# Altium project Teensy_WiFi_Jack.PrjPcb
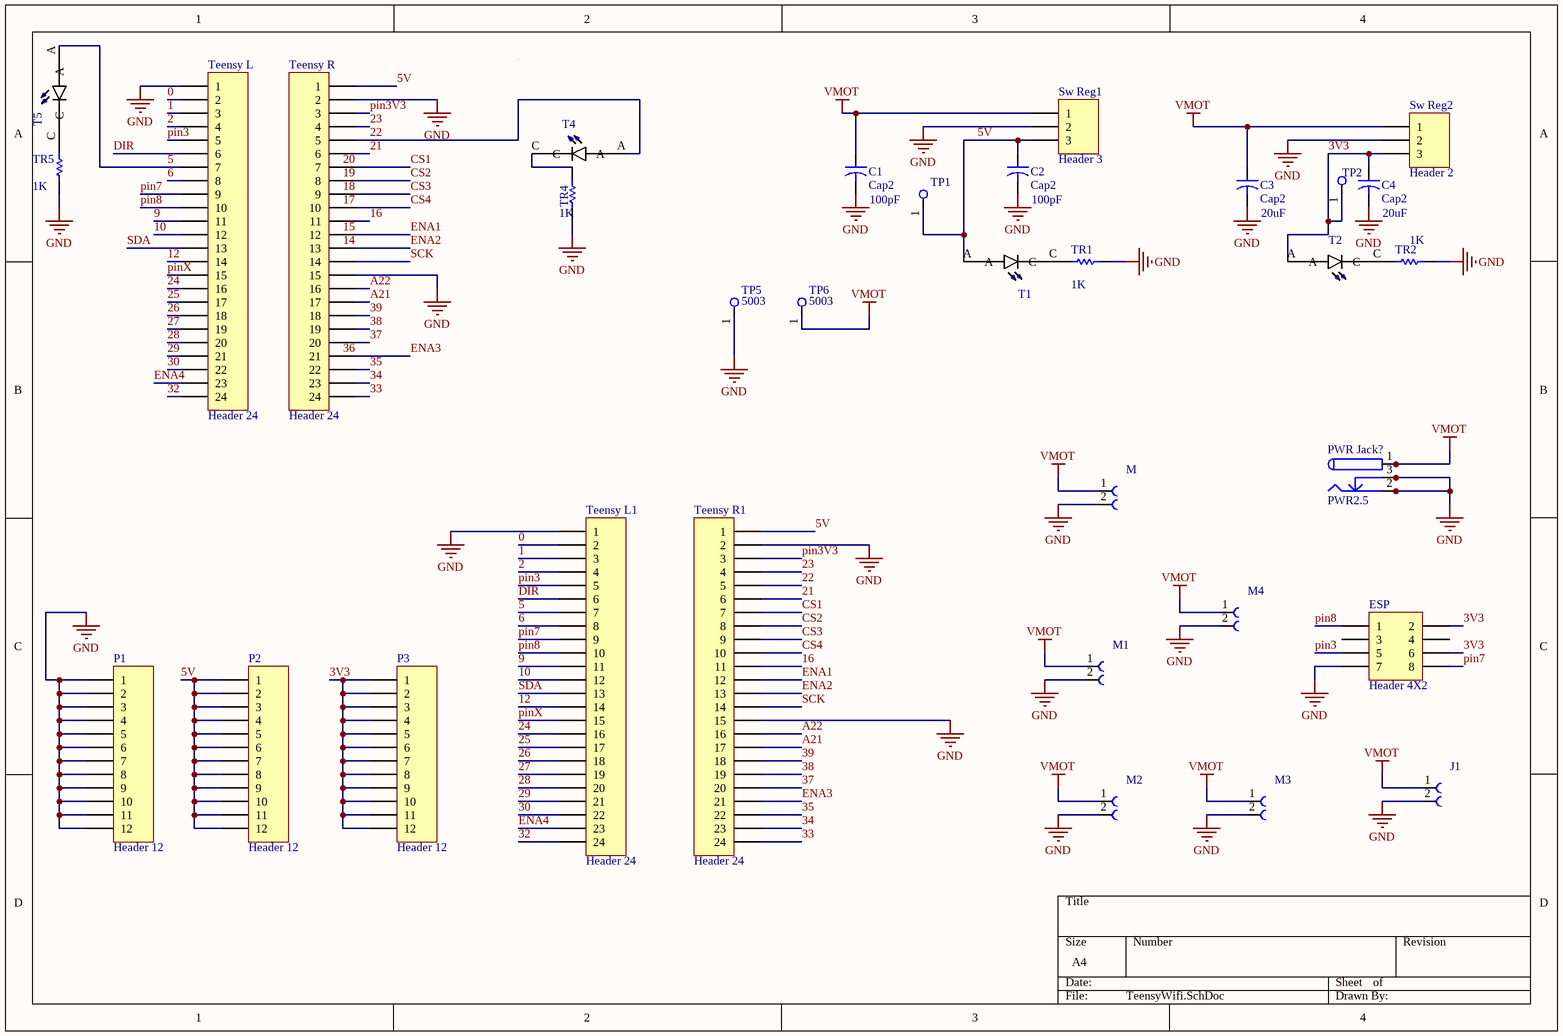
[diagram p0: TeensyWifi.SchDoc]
1 sheet, 33 parts. Net scope: global (net labels, ports and power ports of the same name join across sheets).
Board file: TeensyWifi.PcbDoc

## Sheet TeensyWifi.SchDoc
size A4

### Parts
C1  Cap2  value 100pF  [CAPR5-4X5]
C2  Cap2  value 100pF  [CAPR5-4X5]
C3  Cap2  value 20uF  [CAPR5-4X5]
C4  Cap2  value 20uF  [CAPR5-4X5]
ESP  Header 4X2  [HDR2X4]
J1  (no value)  [691102710002]
M  (no value)  [691102710002]
M1  (no value)  [691102710002]
M2  (no value)  [691102710002]
M3  (no value)  [691102710002]
M4  (no value)  [691102710002]
P1  Header 12  [HDR1X12]
P2  Header 12  [HDR1X12]
P3  Header 12  [HDR1X12]
PWR_Jack  PWR2.5  [KLD-0202]
Sw_Reg1  Header 3  [HDR1X3]
Sw_Reg2  Header 2  [HDR1X3]
T1  LTL-1CHYE  [LED_LTL-1CHYE_LTL-1CHYE(Primary)]  (value not drawn)
T2  LTL-1CHYE  [LED_LTL-1CHYE_LTL-1CHYE(Primary)]  (value not drawn)
T4  LTL-1CHYE  [LED_LTL-1CHYE_LTL-1CHYE(Primary)]  (value not drawn)
T5  LTL-1CHYE  [LED_LTL-1CHYE_LTL-1CHYE(Primary)]  (value not drawn)
Teensy_L  Header 24  [HDR1X24]
Teensy_L1  Header 24  [HDR1X24]
Teensy_R  Header 24  [HDR1X24]
Teensy_R1  Header 24  [HDR1X24]
TP1  (no value)  [TPCW51D250H460P]
TP2  (no value)  [TPCW51D250H460P]
TP5  5003  [TPCW51D250H460P]
TP6  5003  [TPCW51D250H460P]
TR1  value 1K  [AXIAL-0.5]
TR2  value 1K  [AXIAL-0.5]
TR4  value 1K  [AXIAL-0.5]
TR5  value 1K  [AXIAL-0.5]

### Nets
GND: C1.2 C2.2 C3.2 C4.2 ESP.7 J1.2 M.2 M1.2 M2.2 M3.2 M4.2 P1.1 P1.2 P1.3 P1.4 P1.5 P1.6 P1.7 P1.8 P1.9 P1.10 P1.11 P1.12 PWR_Jack.2 PWR_Jack.2A PWR_Jack.2B PWR_Jack.3 PWR_Jack.3A PWR_Jack.3B Sw_Reg1.2 Sw_Reg2.2 Teensy_L.1 Teensy_L1.1 Teensy_R.2 Teensy_R.15 Teensy_R1.2 Teensy_R1.15 TP5.1(TP) TR1.1 TR2.1 TR4.1 TR5.1
VMOT: C1.1 C3.1 J1.1 M.1 M1.1 M2.1 M3.1 M4.1 PWR_Jack.1 PWR_Jack.1A PWR_Jack.1B Sw_Reg1.1 Sw_Reg2.1 TP6.1(TP)
0: Teensy_L.2 Teensy_L1.2
1: Teensy_L.3 Teensy_L1.3
2: Teensy_L.4 Teensy_L1.4
3V3: C4.1 ESP.2 ESP.6 P3.1 P3.2 P3.3 P3.4 P3.5 P3.6 P3.7 P3.8 P3.9 P3.10 P3.11 P3.12 Sw_Reg2.3 T2.A TP2.1(TP)
5: T5.A Teensy_L.7 Teensy_L1.7
5V: C2.1 P2.1 P2.2 P2.3 P2.4 P2.5 P2.6 P2.7 P2.8 P2.9 P2.10 P2.11 P2.12 Sw_Reg1.3 T1.A Teensy_R.1 Teensy_R1.1 TP1.1(TP)
6: Teensy_L.8 Teensy_L1.8
9: Teensy_L.11 Teensy_L1.11
10: Teensy_L.12 Teensy_L1.12
12: Teensy_L.14 Teensy_L1.14
16: Teensy_R.11 Teensy_R1.11
21: Teensy_R.6 Teensy_R1.6
22: T4.A Teensy_R.5 Teensy_R1.5
23: Teensy_R.4 Teensy_R1.4
24: Teensy_L.16 Teensy_L1.16
25: Teensy_L.17 Teensy_L1.17
26: Teensy_L.18 Teensy_L1.18
27: Teensy_L.19 Teensy_L1.19
28: Teensy_L.20 Teensy_L1.20
29: Teensy_L.21 Teensy_L1.21
30: Teensy_L.22 Teensy_L1.22
32: Teensy_L.24 Teensy_L1.24
33: Teensy_R.24 Teensy_R1.24
34: Teensy_R.23 Teensy_R1.23
35: Teensy_R.22 Teensy_R1.22
37: Teensy_R.20 Teensy_R1.20
38: Teensy_R.19 Teensy_R1.19
39: Teensy_R.18 Teensy_R1.18
A21: Teensy_R.17 Teensy_R1.17
A22: Teensy_R.16 Teensy_R1.16
CS1: Teensy_R.7 Teensy_R1.7
CS2: Teensy_R.8 Teensy_R1.8
CS3: Teensy_R.9 Teensy_R1.9
CS4: Teensy_R.10 Teensy_R1.10
DIR: Teensy_L.6 Teensy_L1.6
ENA1: Teensy_R.12 Teensy_R1.12
ENA2: Teensy_R.13 Teensy_R1.13
ENA3: Teensy_R.21 Teensy_R1.21
ENA4: Teensy_L.23 Teensy_L1.23
pin3: ESP.5 Teensy_L.5 Teensy_L1.5
pin3V3: Teensy_R.3 Teensy_R1.3
pin7: ESP.8 Teensy_L.9 Teensy_L1.9
pin8: ESP.1 Teensy_L.10 Teensy_L1.10
pinX: Teensy_L.15 Teensy_L1.15
SCK: Teensy_R.14 Teensy_R1.14
SDA: Teensy_L.13 Teensy_L1.13
NetT1_C: T1.C TR1.2
NetT2_C: T2.C TR2.2
NetT4_C: T4.C TR4.2
NetT5_C: T5.C TR5.2

Not connected (* = marked no-connect by the designer): ESP 3 4

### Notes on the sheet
- Labels drawn without touching a wire or pin: 14, 15, 17, 18, 19, 20, 36

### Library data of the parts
C1-C4 = Cap2: Capacitor
ESP = Header 4X2: Header, 4-Pin, Dual row
J1 M M1-M4 = 691102710002: 102 Series 5mm Pitch Straight, PCB Terminal Block, Through Hole, 2 Way; MF: Wurth Electronics
P1-P3 = Header 12: Header, 12-Pin
PWR_Jack = PWR2.5: Low Voltage Power Supply Connector
Sw_Reg1 Sw_Reg2 = Header 3: Header, 3-Pin
T1 T2 T4 T5 = LTL-1CHYE: Yellow 3.1 mm 45Â° Tinted Clear 40 mcd 2.1 V LED Through Hole; MF: Lite-On
Teensy_L Teensy_L1 Teensy_R Teensy_R1 = Header 24: Header, 24-Pin
TP1 TP2 TP5 TP6 = 5003: Test Point; Orange; Thru-Hole; Snap-Fit; SilverPlate; 0.040 in. Dia.; 0.300 In.; MF: Keystone
TR1 TR2 TR4 TR5 = Res Semi: Semiconductor Resistor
